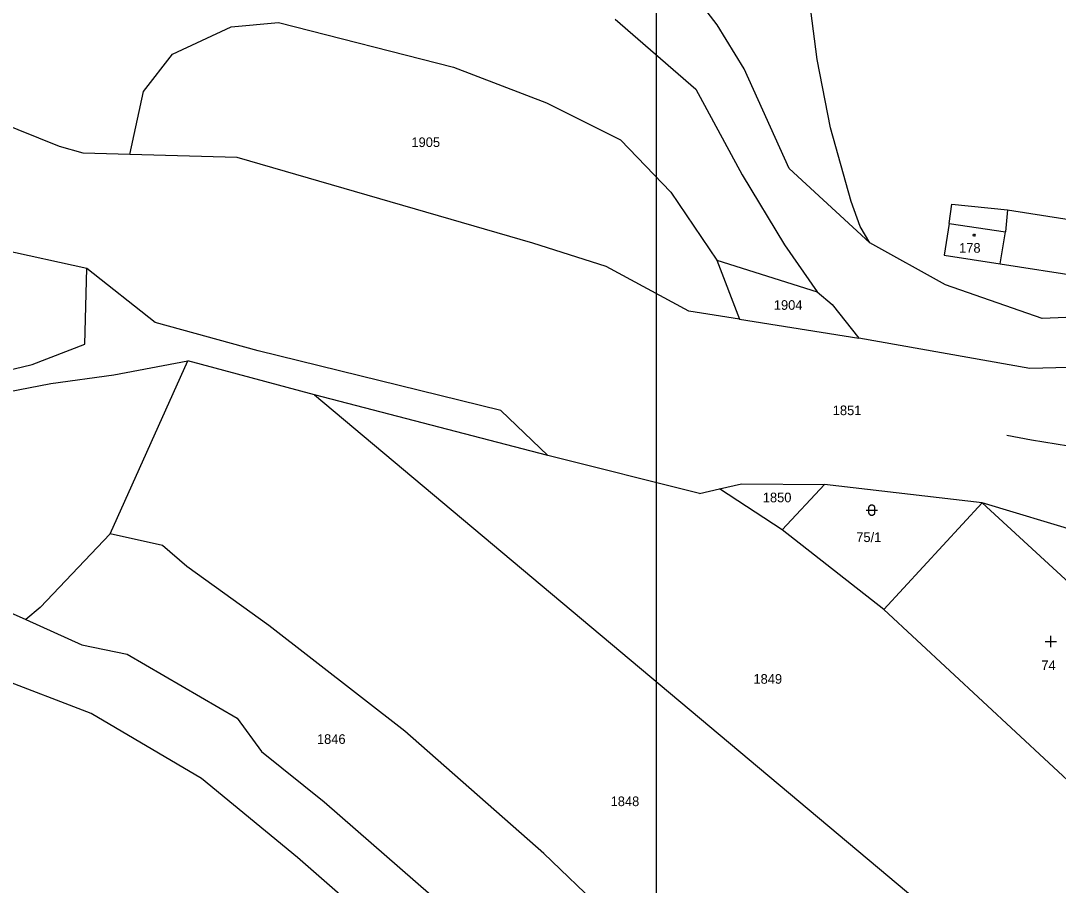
# Model space of a CAD drawing. Extents: x -801853 to -800578, y -1017479 to -1016338.
# Drawn here: x -801671.4 to -801488.1, y -1017325 to -1017172.4 of the extents above; entities that cross this region are included whole.
import ezdxf

# ---------------------------------------------------------------- set-up
doc = ezdxf.new("R2010")
doc.units = 0
for name, color, linetype in [('Default', 7, 'Continuous'), ('KN_HRANICE', 7, 'Continuous'), ('KN_KULTURY', 7, 'Continuous'), ('KN_PARCELY', 7, 'Continuous'), ('KN_SLUCKY', 7, 'Continuous'), ('LEGENDA', 7, 'Continuous'), ('Železniční svršek', 7, 'Continuous')]:
    doc.layers.add(name, color=color, linetype=linetype)

# ---------------------------------------------------------------- blocks, each defined once
blk = doc.blocks.new('315')
at = {"layer": 'Default'}
for p, q in [((0, 0), (0, 2)), ((-1, 1), (1, 1))]:
    blk.add_line(p, q, dxfattribs=at)
blk = doc.blocks.new('316')
at = {"layer": 'Default'}
for points in [[(-0.5, 1.5), (-0.4, 1.79), (-0.15, 1.97), (0.16, 1.97), (0.41, 1.79), (0.51, 1.5), (0.51, 0.5), (0.41, 0.21), (0.16, 0.03), (-0.15, 0.03), (-0.4, 0.21), (-0.5, 0.5), (-0.5, 1.5)], [(-1, 1), (0.27, 1), (1, 1)]]:
    blk.add_lwpolyline(points, dxfattribs=at)
blk = doc.blocks.new('402')
at = {"layer": 'Default'}
blk.add_lwpolyline([(0.09, 0.15), (0.18, 0), (0.09, -0.15), (-0.09, -0.15), (-0.18, 0), (-0.09, 0.15), (0.09, 0.15)], dxfattribs=at)

msp = doc.modelspace()

# ---------------------------------------------------------------- linework, layer by layer
at = {"layer": 'KN_HRANICE'}
for p, q in [((-801548.37, -1017173.06), (-801556.12, -1017162.99)), ((-801530.73, -1017179.18), (-801531.84, -1017170.53)), ((-801634.26, -1017173.42), (-801625.85, -1017172.65)), ((-801625.85, -1017172.65), (-801594.98, -1017180.53)), ((-801566.4, -1017172.05), (-801552.14, -1017184.41)), ((-801644.6, -1017178.24), (-801634.26, -1017173.42)), ((-801543.63, -1017180.82), (-801548.37, -1017173.06)), ((-801649.74, -1017184.84), (-801644.6, -1017178.24)), ((-801528.39, -1017191.25), (-801530.73, -1017179.18)), ((-801594.98, -1017180.53), (-801578.52, -1017186.87)), ((-801535.65, -1017198.46), (-801543.63, -1017180.82)), ((-801652.13, -1017195.98), (-801649.74, -1017184.84)), ((-801552.14, -1017184.41), (-801543.98, -1017199.57)), ((-801578.52, -1017186.87), (-801565.48, -1017193.37)), ((-801664.54, -1017194.54), (-801676.49, -1017189.78)), ((-801524.73, -1017204.29), (-801528.39, -1017191.25)), ((-801660.4, -1017195.75), (-801664.54, -1017194.54)), ((-801565.48, -1017193.37), (-801556.54, -1017202.62)), ((-801652.13, -1017195.98), (-801660.4, -1017195.75)), ((-801633.16, -1017196.52), (-801652.13, -1017195.98)), ((-801580.92, -1017211.61), (-801633.16, -1017196.52)), ((-801521.39, -1017211.55), (-801535.65, -1017198.46)), ((-801543.98, -1017199.57), (-801536.47, -1017211.89)), ((-801556.54, -1017202.62), (-801548.42, -1017214.61)), ((-801523.11, -1017208.68), (-801524.73, -1017204.29)), ((-801507.39, -1017208.16), (-801506.92, -1017204.72)), ((-801506.92, -1017204.72), (-801497.12, -1017205.74)), ((-801497.12, -1017205.74), (-801497.46, -1017209.65)), ((-801497.12, -1017205.74), (-801475.51, -1017209.1)), ((-801521.39, -1017211.55), (-801523.11, -1017208.68)), ((-801507.39, -1017208.16), (-801508.3, -1017213.74)), ((-801498.4, -1017215.28), (-801497.46, -1017209.65)), ((-801659.71, -1017216.08), (-801674.74, -1017212.79)), ((-801568.01, -1017215.75), (-801580.92, -1017211.61)), ((-801536.47, -1017211.89), (-801530.7, -1017220.23)), ((-801508.05, -1017218.99), (-801521.39, -1017211.55)), ((-801548.42, -1017214.61), (-801530.7, -1017220.23)), ((-801548.42, -1017214.61), (-801544.43, -1017225.03)), ((-801508.3, -1017213.74), (-801498.4, -1017215.28)), ((-801660.09, -1017229.47), (-801659.71, -1017216.08)), ((-801647.64, -1017225.66), (-801659.71, -1017216.08)), ((-801553.36, -1017223.62), (-801568.01, -1017215.75)), ((-801498.4, -1017215.28), (-801483.24, -1017217.64)), ((-801530.7, -1017220.23), (-801528.05, -1017222.47)), ((-801490.95, -1017224.93), (-801508.05, -1017218.99)), ((-801544.43, -1017225.03), (-801553.36, -1017223.62)), ((-801528.05, -1017222.47), (-801523.33, -1017228.37)), ((-801629.44, -1017230.66), (-801647.64, -1017225.66)), ((-801544.43, -1017225.03), (-801523.33, -1017228.37)), ((-801482.16, -1017224.57), (-801490.95, -1017224.93)), ((-801669.39, -1017233.06), (-801660.09, -1017229.47)), ((-801493.13, -1017233.77), (-801523.33, -1017228.37)), ((-801586.61, -1017241.17), (-801629.44, -1017230.66)), ((-801679.68, -1017235.48), (-801669.39, -1017233.06)), ((-801655.6, -1017262.96), (-801641.91, -1017232.42)), ((-801654.99, -1017234.85), (-801641.91, -1017232.42)), ((-801619.51, -1017238.39), (-801641.91, -1017232.42)), ((-801666.12, -1017236.42), (-801654.99, -1017234.85)), ((-801481.63, -1017233.42), (-801493.13, -1017233.77)), ((-801678.68, -1017238.81), (-801666.12, -1017236.42)), ((-801619.51, -1017238.39), (-801481.95, -1017353.71)), ((-801578.28, -1017249.11), (-801619.51, -1017238.39)), ((-801578.28, -1017249.11), (-801586.61, -1017241.17)), ((-801551.48, -1017255.81), (-801578.28, -1017249.11)), ((-801551.48, -1017255.81), (-801547.98, -1017255)), ((-801547.98, -1017255), (-801544.09, -1017254.11)), ((-801536.89, -1017262.22), (-801547.98, -1017255)), ((-801544.09, -1017254.11), (-801529.45, -1017254.24)), ((-801529.45, -1017254.24), (-801536.89, -1017262.22)), ((-801501.56, -1017257.45), (-801529.45, -1017254.24)), ((-801518.94, -1017276.33), (-801501.56, -1017257.45)), ((-801477.73, -1017264.63), (-801501.56, -1017257.45)), ((-801466.82, -1017289.45), (-801501.56, -1017257.45)), ((-801518.94, -1017276.33), (-801536.89, -1017262.22)), ((-801655.6, -1017262.96), (-801668, -1017275.97)), ((-801646.39, -1017265.01), (-801655.6, -1017262.96)), ((-801642.06, -1017268.74), (-801646.39, -1017265.01)), ((-801627.56, -1017279.15), (-801642.06, -1017268.74)), ((-801678.51, -1017274.48), (-801670.52, -1017278.09)), ((-801668, -1017275.97), (-801670.52, -1017278.09)), ((-801473.28, -1017318.78), (-801518.94, -1017276.33)), ((-801670.52, -1017278.09), (-801660.59, -1017282.57)), ((-801603.57, -1017297.8), (-801627.56, -1017279.15)), ((-801658.95, -1017294.66), (-801692.48, -1017281.81)), ((-801660.59, -1017282.57), (-801652.6, -1017284.2)), ((-801652.6, -1017284.2), (-801633.2, -1017295.47)), ((-801639.5, -1017306.13), (-801658.95, -1017294.66)), ((-801633.2, -1017295.47), (-801628.86, -1017301.38)), ((-801579.02, -1017319.41), (-801603.57, -1017297.8)), ((-801628.86, -1017301.38), (-801617.81, -1017310.3)), ((-801622.51, -1017320.08), (-801639.5, -1017306.13)), ((-801617.81, -1017310.3), (-801591.97, -1017332.75)), ((-801568.75, -1017329.21), (-801579.02, -1017319.41)), ((-801590.96, -1017347.71), (-801622.51, -1017320.08))]:
    msp.add_line(p, q, dxfattribs=at)
at = {"layer": 'KN_SLUCKY'}
msp.add_line((-801507.39, -1017208.16), (-801497.46, -1017209.65), dxfattribs=at)
at = {"layer": 'LEGENDA'}
msp.add_lwpolyline([(-801559.16, -1017339.08), (-800718.16, -1017339.08), (-800718.16, -1016745.08), (-801559.16, -1016745.08)], close=True, dxfattribs=at)
at = {"layer": 'Železniční svršek'}
msp.add_arc((-801431.93, -1016905.94), 345.8, 259.1164, 305.4132, dxfattribs=at)

# ---------------------------------------------------------------- block references
at = {"layer": 'KN_KULTURY'}
for name, p in [('402', (-801502.99, -1017210.21)), ('316', (-801521.08, -1017259.77)), ('315', (-801489.43, -1017282.97))]:
    msp.add_blockref(name, p, dxfattribs=at)

# ---------------------------------------------------------------- texts
at = {"layer": 'KN_PARCELY'}
for s, p in [('1905', (-801602.39, -1017194.65)), ('178', (-801505.64, -1017213.31)), ('1904', (-801538.37, -1017223.39)), ('1851', (-801527.96, -1017241.99)), ('1850', (-801540.32, -1017257.38)), ('75/1', (-801523.81, -1017264.4)), ('74', (-801491.11, -1017287.01)), ('1849', (-801541.97, -1017289.42)), ('1846', (-801619.08, -1017300.04)), ('1848', (-801567.2, -1017311.03))]:
    msp.add_text(s, height=1.7, dxfattribs=at).set_placement(p)

doc.saveas('drawing.dxf')
